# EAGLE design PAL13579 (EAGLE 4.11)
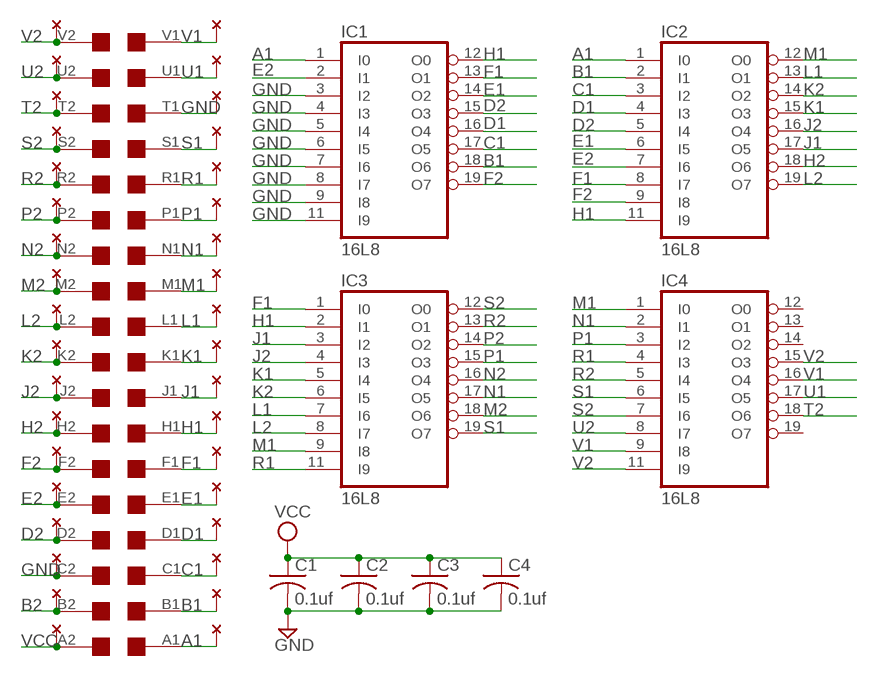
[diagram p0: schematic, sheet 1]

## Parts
C1  0.1uf  C-US050-025X075  [C050-025X075]
C2  0.1uf  C-US050-025X075  [C050-025X075]
C3  0.1uf  C-US050-025X075  [C050-025X075]
C4  0.1uf  C-US050-025X075  [C050-025X075]
IC1  16L8  [DIL20]
IC2  16L8  [DIL20]
IC3  16L8  [DIL20]
IC4  16L8  [DIL20]
U$1  EDGE-2  [EDGE-CON2]
U$4  THRU-HOLE2  [THRU-HOLEB]

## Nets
A1: IC1.1(I0) IC2.1(I0) U$1.A1 U$4.A2
B1: IC1.18(O6) IC2.2(I1) U$1.B1 U$4.B2
B2: U$1.B2 U$4.B1
C1: IC1.17(O5) IC2.3(I2) U$1.C1 U$4.C2
D1: IC1.16(O4) IC2.4(I3) U$1.D1 U$4.D2
D2: IC1.15(O3) IC2.5(I4) U$1.D2 U$4.D1
E1: IC1.14(O2) IC2.6(I5) U$1.E1 U$4.E2
E2: IC1.2(I1) IC2.7(I6) U$1.E2 U$4.E1
F1: IC1.13(O1) IC2.8(I7) IC3.1(I0) U$1.F1 U$4.F2
F2: IC1.19(O7) IC2.9(I8) U$1.F2 U$4.F1
GND [supply]: C1.2 C2.2 C3.2 C4.2 IC1.3(I2) IC1.4(I3) IC1.5(I4) IC1.6(I5) IC1.7(I6) IC1.8(I7) IC1.9(I8) IC1.11(I9) U$1.C2 U$1.T1 U$4.C1 U$4.T2
H1: IC1.12(O0) IC2.11(I9) IC3.2(I1) U$1.H1 U$4.H2
H2: IC2.18(O6) U$1.H2 U$4.H1
J1: IC2.17(O5) IC3.3(I2) U$1.J1 U$4.J2
J2: IC2.16(O4) IC3.4(I3) U$1.J2 U$4.J1
K1: IC2.15(O3) IC3.5(I4) U$1.K1 U$4.K2
K2: IC2.14(O2) IC3.6(I5) U$1.K2 U$4.K1
L1: IC2.13(O1) IC3.7(I6) U$1.L1 U$4.L2
L2: IC2.19(O7) IC3.8(I7) U$1.L2 U$4.L1
M1: IC2.12(O0) IC3.9(I8) IC4.1(I0) U$1.M1 U$4.M2
M2: IC3.18(O6) U$1.M2 U$4.M1
N1: IC3.17(O5) IC4.2(I1) U$1.N1 U$4.N2
N2: IC3.16(O4) U$1.N2 U$4.N1
P1: IC3.15(O3) IC4.3(I2) U$1.P1 U$4.P2
P2: IC3.14(O2) U$1.P2 U$4.P1
R1: IC3.11(I9) IC4.4(I3) U$1.R1 U$4.R2
R2: IC3.13(O1) IC4.5(I4) U$1.R2 U$4.R1
S1: IC3.19(O7) IC4.6(I5) U$1.S1 U$4.S2
S2: IC3.12(O0) IC4.7(I6) U$1.S2 U$4.S1
T2: IC4.18(O6) U$1.T2 U$4.T1
U1: IC4.17(O5) U$1.U1 U$4.U2
U2: IC4.8(I7) U$1.U2 U$4.U1
V1: IC4.9(I8) IC4.16(O4) U$1.V1 U$4.V2
V2: IC4.11(I9) IC4.15(O3) U$1.V2 U$4.V1
VCC [supply]: C1.1 C2.1 C3.1 C4.1 U$1.A2 U$4.A1
Unconnected: IC4.12(O0) IC4.13(O1) IC4.14(O2) IC4.19(O7)

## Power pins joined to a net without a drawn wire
GND: IC1.10(GND) IC2.10(GND) IC3.10(GND) IC4.10(GND)
VCC: IC1.20(VCC) IC2.20(VCC) IC3.20(VCC) IC4.20(VCC)

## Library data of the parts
C1-C4 = rcl:C-US: CAPACITOR, American symbol
IC1-IC4 = pal:16L8: PAL
U$1 = dec-con:EDGE-2: Double-Sided DEC edge connector.
U$4 = dec-con:THRU-HOLE2: Thru-Hole addition to double-sided edge connector.

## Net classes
1 supply: width 0.381 mm

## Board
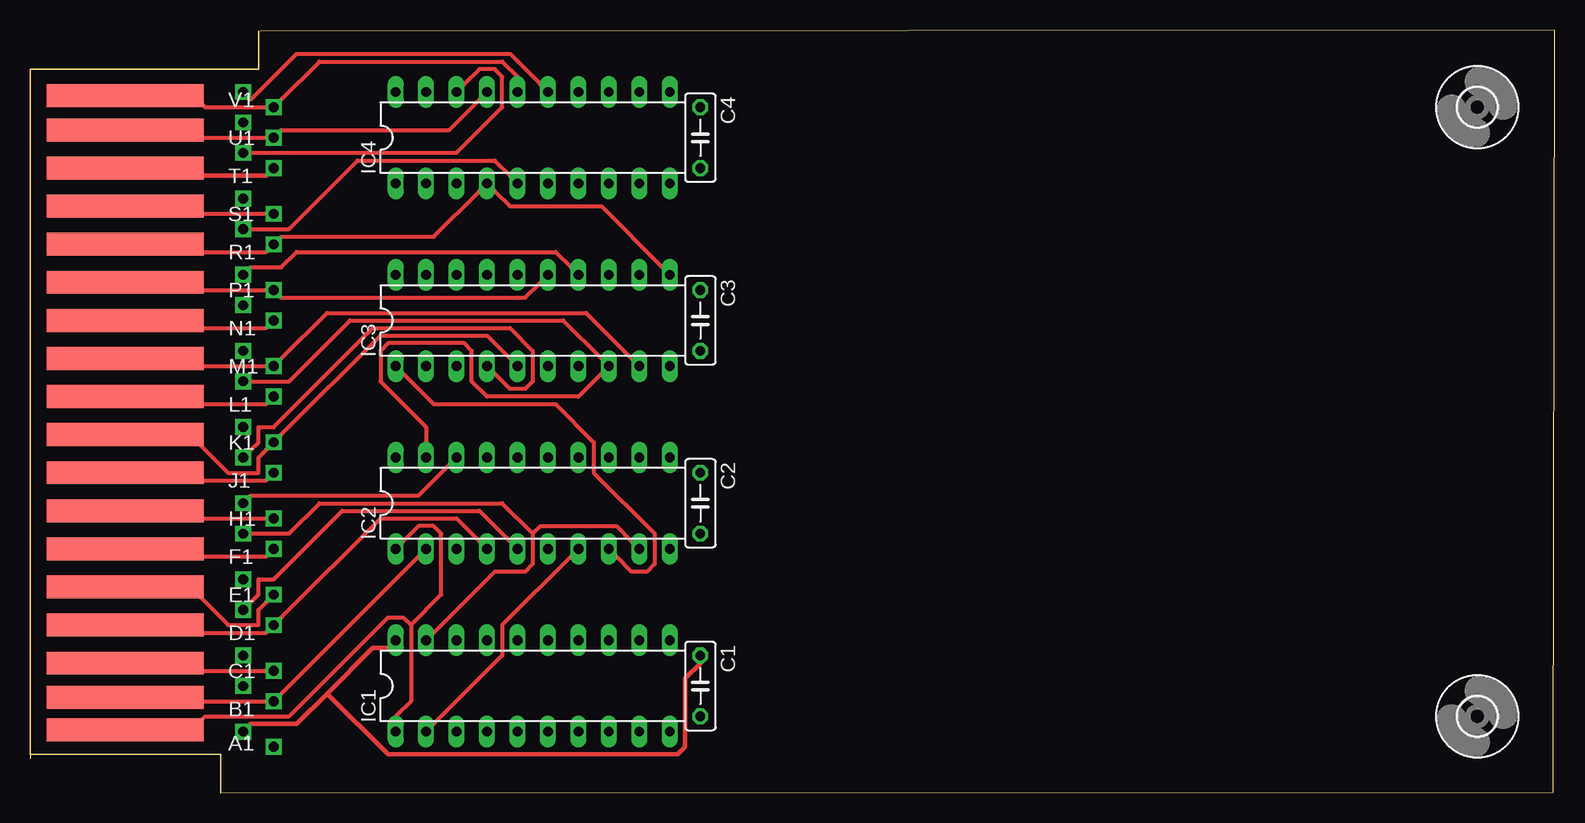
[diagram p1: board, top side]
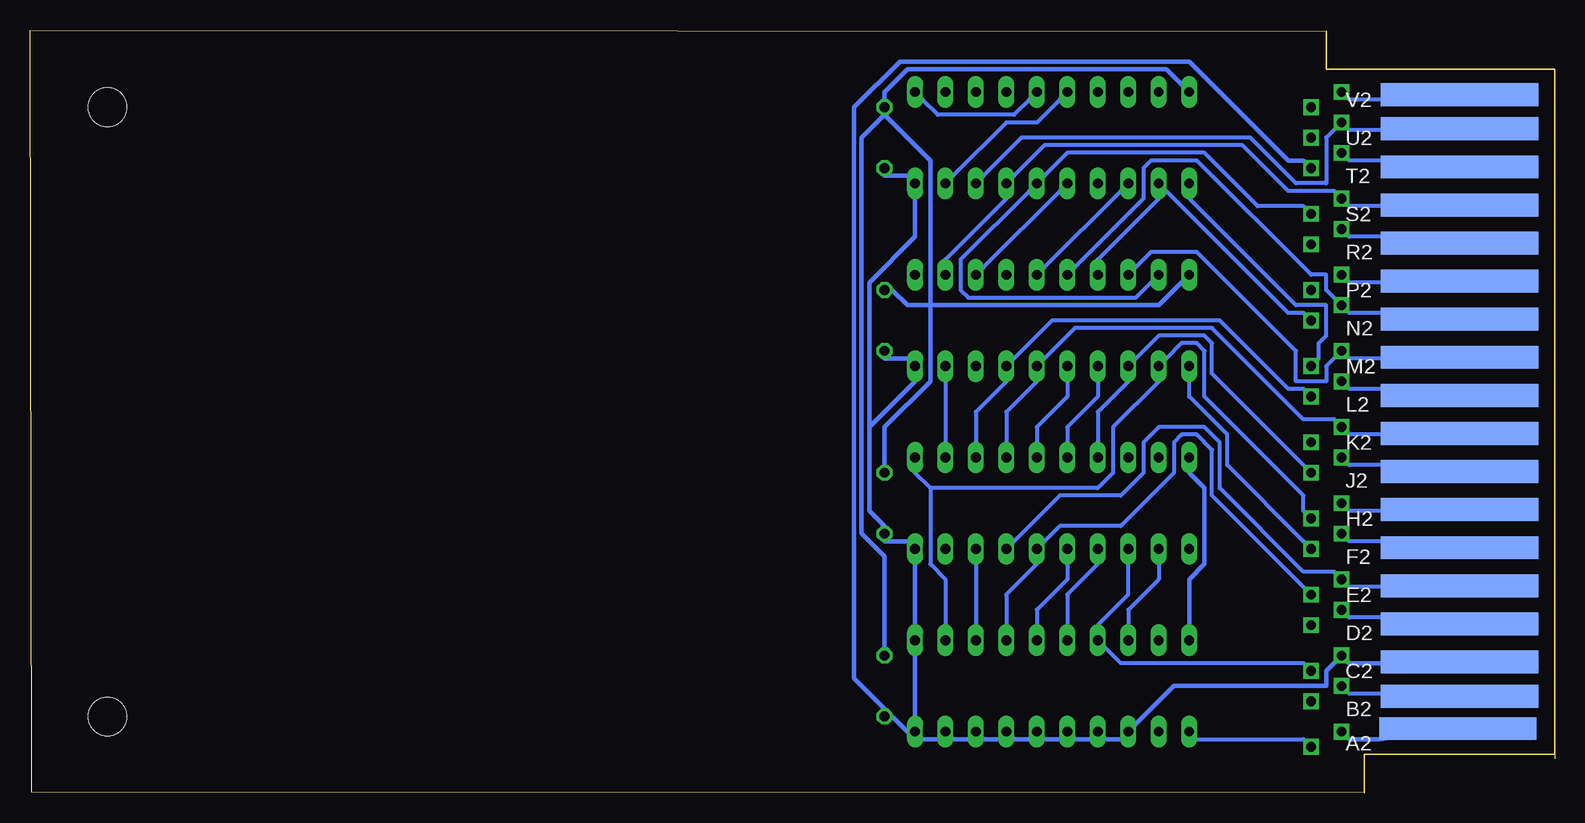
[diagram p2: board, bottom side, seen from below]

Size 127.11 x 63.59 mm. Coordinates in mm from the lower left corner, seen from the top.
Outline: 15.88,0 126.98,0.04 127.11,63.59 19.18,63.5
Outline: 0.01,59.65 0.01,2.83
Copper layers (1*16): Top 0.035mm / dielectric 1.5mm / Bottom 0.035mm
Design rules "10mils": minimum track width 13mil, minimum drill 28mil, track to track 10mil, track to pad 10mil, pad to pad 10mil, via to via 10mil, smd to smd 10mil, copper to edge 40mil, drill to drill 10mil, minimum pad ring 10mil, minimum via ring 8mil, stop-mask expansion 0mil, vias tented up to drill 0mil, thermal gap 10mil

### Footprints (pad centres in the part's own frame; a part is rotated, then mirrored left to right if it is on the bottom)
C050-025X075 = drill 0.813 octagon: 1 -2.54,0; 2 2.54,0
DIL20 = drill 0.813 long: 1 -11.43,-3.81; 2 -8.89,-3.81; 3 -6.35,-3.81; 4 -3.81,-3.81; 5 -1.27,-3.81; 6 1.27,-3.81; 7 3.81,-3.81; 8 6.35,-3.81; 9 8.89,-3.81; 10 11.43,-3.81; 11 11.43,3.81; 12 8.89,3.81; 13 6.35,3.81; 14 3.81,3.81; 15 1.27,3.81; 16 -1.27,3.81; 17 -3.81,3.81; 18 -6.35,3.81; 19 -8.89,3.81; 20 -11.43,3.81
EDGE-CON2 = smd 13.106 x 1.905: A1 7.938,5.239; B1 7.938,7.938; C1 7.938,10.795; D1 7.938,13.97; E1 7.938,17.145; F1 7.938,20.32; H1 7.938,23.495; J1 7.938,26.67; K1 7.938,29.845; L1 7.938,33.02; M1 7.938,36.195; N1 7.938,39.37; P1 7.938,42.545; R1 7.938,45.72; S1 7.938,48.895; T1 7.938,52.07; U1 7.938,55.245; V1 7.938,58.102 | smd 13.106 x 1.905 bottom: A2 8.096,5.34; B2 7.938,8.039; C2 7.938,10.897; D2 7.938,14.072; E2 7.938,17.247; F2 7.938,20.422; H2 7.938,23.597; J2 7.938,26.772; K2 7.938,29.947; L2 7.938,33.122; M2 7.938,36.297; N2 7.938,39.472; P2 7.938,42.647; R2 7.938,45.822; S2 7.938,48.997; T2 7.938,52.172; U2 7.938,55.347; V2 7.938,58.204
3,2 = hole 3.2: 0,0
THRU-HOLEB = drill 0.813 square: A1 17.78,5.08; A2 20.32,3.81; B1 17.78,8.89; B2 20.32,7.62; C1 17.78,11.43; C2 20.32,10.16; D1 17.78,15.24; D2 20.32,13.97; E1 17.78,17.78; E2 20.32,16.51; F1 17.78,21.59; F2 20.32,20.32; H1 17.78,24.13; H2 20.32,22.86; J1 17.78,27.94; J2 20.32,26.67; K1 17.78,30.48; K2 20.32,29.21; L1 17.78,34.29; L2 20.32,33.02; M1 17.78,36.83; M2 20.32,35.56; N1 17.78,40.64; N2 20.32,39.37; P1 17.78,43.18; P2 20.32,41.91; R1 17.78,46.99; R2 20.32,45.72; S1 17.78,49.53; S2 20.32,48.26; T1 17.78,53.34; T2 20.32,52.07; U1 17.78,55.88; U2 20.32,54.61; V1 17.78,58.42; V2 20.32,57.15

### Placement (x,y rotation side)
C1  55.88,8.89 270 top
C2  55.88,24.13 270 top
C3  55.88,39.37 270 top
C4  55.88,54.61 270 top
IC1  41.91,8.89 0 top
IC2  41.91,24.13 0 top
IC3  41.91,39.37 0 top
IC4  41.91,54.61 0 top
U$1  0,0 0 top
U$2  [3,2]  120.65,6.35 0 top
U$3  [3,2]  120.65,57.15 0 top
U$4  0,0 0 top

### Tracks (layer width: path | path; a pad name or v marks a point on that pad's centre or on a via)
A1
  Top 0.33: 31.75,13.97 34.29,16.51 34.29,21.59 33.66,22.23 32.38,22.23 31.11,20.95 IC2.1 | 31.75,13.97 31.75,7.62 30.48,6.35 IC1.1 | 31.75,13.97 31.11,14.61 29.84,14.61 21.59,6.35 14.61,6.35 13.97,5.71 U$1.A1
  Bottom 0.33: U$4.A2 20.95,4.45 29.84,4.45 IC1.1
B1
  Top 0.33: U$1.B1 13.97,7.62 19.68,7.62 U$4.B2 20.95,8.26 32.38,19.68 IC2.2
  Bottom 0.33: IC1.18 35.56,13.97 35.56,15.24 33.02,17.78 33.02,19.05 IC2.2
B2
  Bottom 0.33: U$4.B1 17.14,8.26 13.97,8.26 U$1.B2
C1
  Top 0.33: U$4.C2 19.68,10.16 13.97,10.16 U$1.C1
  Bottom 0.33: U$4.C2 20.95,10.79 36.2,10.79 37.47,12.06 IC1.17 38.1,13.97 35.56,16.51 35.56,19.05 IC2.3
D1
  Top 0.33: U$1.D1 13.97,13.34 19.68,13.34 U$4.D2 20.95,14.61 29.21,22.86 35.56,22.86 37.47,20.95 IC2.4
  Bottom 0.33: IC1.16 40.64,13.97 40.64,16.51 38.1,19.05 IC2.4
D2
  Top 0.33: IC2.5 40.01,20.95 37.47,23.5 26.04,23.5 20.32,17.78 19.05,17.78 19.05,16.51 18.41,15.88 U$4.D1
  Bottom 0.33: IC2.5 40.64,19.05 40.64,17.78 43.18,15.24 43.18,13.97 IC1.15 | U$4.D1 17.14,14.61 13.97,14.61 U$1.D2
E1
  Top 0.33: U$1.E1 13.97,16.51 16.51,13.97 19.05,13.97 19.05,15.24 19.68,15.88 U$4.E2
  Bottom 0.33: U$4.E2 20.95,17.14 28.57,24.77 28.57,28.57 29.84,29.84 31.11,29.84 31.75,29.21 31.75,26.67 36.2,22.23 41.27,22.23 42.55,20.95 IC2.6 43.18,19.05 45.72,16.51 45.72,13.97 IC1.14
E2
  Top 0.33: IC1.2 33.66,5.71 39.37,11.43 39.37,13.97 45.09,19.68 IC2.7
  Bottom 0.33: U$1.E2 13.97,17.14 17.14,17.14 U$4.E1 18.41,18.41 20.95,18.41 27.94,25.4 27.94,29.21 29.21,30.48 33.02,30.48 34.29,29.21 34.29,26.67 36.2,24.77 41.27,24.77 45.09,20.95 IC2.7
F1
  Top 0.33: IC2.8 48.9,19.68 50.16,18.41 51.44,18.41 52.07,19.05 52.07,21.59 46.99,26.67 46.99,29.21 43.81,32.38 33.66,32.38 31.11,34.92 IC3.1 | U$1.F1 13.97,19.68 19.68,19.68 U$4.F2
  Bottom 0.33: IC1.13 48.26,13.97 48.26,19.05 IC2.8 | U$4.F2 20.95,20.95 27.3,27.3 27.3,29.84 30.48,33.02 30.48,34.29 IC3.1
F2
  Top 0.33: 41.91,21.59 41.91,19.05 41.27,18.41 38.73,18.41 33.66,13.34 IC1.19 | 41.91,21.59 42.55,22.23 48.9,22.23 50.16,20.95 IC2.9 | 41.91,21.59 39.37,24.13 24.13,24.13 21.59,21.59 18.41,21.59 U$4.F1
  Bottom 0.33: U$4.F1 17.14,20.95 13.97,20.95 U$1.F2
GND
  Top 0.381: U$4.T2 19.68,51.44 13.97,51.44 U$1.T1
  Bottom 0.381: U$1.C2 13.97,10.79 17.14,10.79 U$4.C1 18.41,10.79 19.05,10.16 19.05,8.89 31.75,8.89 34.92,5.71 IC1.3 36.2,4.45 37.47,4.45 IC1.4 38.73,4.45 40.01,4.45 IC1.5 41.27,4.45 42.55,4.45 IC1.6 43.81,4.45 45.09,4.45 IC1.7 46.35,4.45 47.62,4.45 IC1.8 48.9,4.45 50.16,4.45 IC1.9 51.44,4.45 52.7,4.45 IC1.10 | C4.2 55.88,51.44 53.98,51.44 IC4.10 53.34,49.53 53.34,46.35 57.15,42.55 57.15,30.48 | C3.2 55.88,36.2 53.98,36.2 IC3.10 53.34,34.29 57.15,30.48 | IC1.10 53.98,5.08 55.24,6.35 C1.2 55.88,6.99 58.42,9.53 58.42,57.15 54.61,60.96 30.48,60.96 22.23,52.7 20.95,52.7 U$4.T2 | IC1.10 53.34,6.35 53.34,11.43 IC1.11 53.34,13.97 53.34,19.05 IC2.10 53.98,20.95 55.88,20.95 C2.2 55.88,22.23 57.15,23.5 57.15,30.48
H1
  Top 0.33: U$1.H1 13.97,22.86 19.68,22.86 U$4.H2
  Bottom 0.33: 52.07,25.4 52.07,19.05 50.8,17.78 50.8,13.97 IC1.12 | 52.07,25.4 53.34,26.67 IC2.11 | U$4.H2 20.95,23.5 20.95,24.77 29.21,33.02 29.21,36.83 29.84,37.47 31.11,37.47 32.38,36.2 IC3.2 33.02,34.29 36.83,30.48 36.83,26.67 38.1,25.4 52.07,25.4
H2
  Top 0.33: IC2.18 34.92,27.3 32.38,24.77 18.41,24.77 U$4.H1
  Bottom 0.33: U$4.H1 17.14,23.5 13.97,23.5 U$1.H2
J1
  Top 0.33: U$4.J2 19.68,26.04 13.97,26.04 U$1.J1
  Bottom 0.33: U$4.J2 20.95,27.3 28.57,34.92 28.57,37.47 29.21,38.1 33.02,38.1 34.92,36.2 IC3.3 35.56,34.29 38.1,31.75 38.1,29.21 IC2.17
J2
  Top 0.33: IC3.4 38.73,34.92 40.01,33.66 41.27,33.66 41.91,34.29 41.91,36.83 40.01,38.73 28.57,38.73 20.32,30.48 19.05,30.48 19.05,29.21 18.41,28.57 U$4.J1
  Bottom 0.33: IC3.4 38.1,34.29 38.1,33.02 40.64,30.48 40.64,29.21 IC2.16 | U$4.J1 17.14,27.3 13.97,27.3 U$1.J2
K1
  Top 0.33: U$1.K1 13.97,29.21 16.51,26.67 19.05,26.67 19.05,27.94 19.68,28.57 U$4.K2 20.95,29.84 29.21,38.1 38.1,38.1 40.01,36.2 IC3.5
  Bottom 0.33: IC3.5 40.64,34.29 40.64,33.02 43.18,30.48 43.18,29.21 IC2.15
K2
  Bottom 0.33: IC2.14 45.72,29.21 45.72,31.75 43.18,34.29 IC3.6 42.55,36.2 40.01,38.73 28.57,38.73 20.95,31.11 18.41,31.11 U$4.K1 17.14,29.84 13.97,29.84 U$1.K2
L1
  Top 0.33: U$1.L1 13.97,32.38 19.68,32.38 U$4.L2
  Bottom 0.33: U$4.L2 20.95,33.66 22.23,33.66 27.94,39.37 41.91,39.37 45.09,36.2 IC3.7 45.72,34.29 48.26,31.75 48.26,29.21 IC2.13
L2
  Top 0.33: IC2.19 33.02,29.21 33.02,30.48 29.21,34.29 29.21,36.83 29.84,37.47 36.2,37.47 36.83,36.83 36.83,34.29 38.1,33.02 45.72,33.02 47.62,34.92 IC3.8 47.62,36.2 44.45,39.37 26.67,39.37 21.59,34.29 18.41,34.29 U$4.L1
  Bottom 0.33: U$4.L1 17.14,33.66 13.97,33.66 U$1.L2
M1
  Top 0.33: IC3.9 50.16,36.2 46.35,40.01 24.77,40.01 20.95,36.2 U$4.M2 19.68,35.56 13.97,35.56 U$1.M1
  Bottom 0.33: IC2.12 50.8,29.21 50.8,34.29 IC3.9 | U$4.M2 19.68,36.2 19.68,37.47 19.05,38.1 19.05,40.64 21.59,40.64 30.48,49.53 IC4.1
M2
  Bottom 0.33: U$1.M2 13.97,36.2 17.14,36.2 U$4.M1 18.41,36.2 19.05,35.56 19.05,34.29 21.59,34.29 21.59,36.83 29.84,45.09 33.66,45.09 34.92,43.81 IC3.18
N1
  Top 0.33: U$4.N2 19.68,38.73 13.97,38.73 U$1.N1
  Bottom 0.33: U$4.N2 20.95,40.01 22.23,40.01 32.38,50.16 IC4.2 33.02,49.53 38.1,44.45 IC3.17
N2
  Bottom 0.33: U$1.N2 13.97,40.01 17.14,40.01 U$4.N1 18.41,41.27 19.05,41.91 19.05,43.18 20.32,43.18 29.84,52.7 33.66,52.7 34.29,52.07 34.29,49.53 40.01,43.81 IC3.16
P1
  Top 0.33: U$1.P1 13.97,41.91 19.68,41.91 U$4.P2 20.95,41.27 41.27,41.27 42.55,42.55 IC3.15
  Bottom 0.33: IC3.15 42.55,43.81 36.2,50.16 IC4.3
P2
  Top 0.33: IC3.14 45.09,43.81 43.81,45.09 22.23,45.09 20.95,43.81 18.41,43.81 U$4.P1
  Bottom 0.33: U$4.P1 17.14,42.55 13.97,42.55 U$1.P2
R1
  Top 0.33: IC3.11 52.7,43.81 47.62,48.9 40.01,48.9 38.73,50.16 IC4.4 37.47,50.16 33.66,46.35 20.95,46.35 U$4.R2 19.68,45.09 13.97,45.09 U$1.R1
R2
  Top 0.33: IC4.5 40.01,51.44 38.73,52.7 27.3,52.7 21.59,46.99 18.41,46.99 U$4.R1
  Bottom 0.33: IC3.13 47.62,43.81 41.27,50.16 IC4.5 | U$4.R1 17.14,46.35 13.97,46.35 U$1.R2
S1
  Top 0.33: U$1.S1 13.97,48.26 19.68,48.26 U$4.S2
  Bottom 0.33: U$4.S2 20.95,48.9 24.77,48.9 29.21,53.34 40.64,53.34 42.55,51.44 IC4.6 43.81,50.16 49.53,44.45 49.53,41.91 48.9,41.27 34.92,41.27 33.66,42.55 IC3.19
S2
  Bottom 0.33: IC3.12 50.8,44.45 45.72,49.53 IC4.7 45.09,51.44 42.55,53.98 26.04,53.98 22.23,50.16 18.41,50.16 U$4.S1 17.14,48.9 13.97,48.9 U$1.S2
T2
  Top 0.33: IC4.18 36.2,59.05 37.47,60.33 38.73,60.33 39.37,59.69 39.37,57.15 35.56,53.34 18.41,53.34 U$4.T1
  Bottom 0.33: U$4.T1 17.14,52.7 13.97,52.7 U$1.T2
U1
  Top 0.33: U$1.U1 13.97,54.61 19.68,54.61 U$4.U2 20.95,55.24 34.92,55.24 37.47,57.78 IC4.17
U2
  Bottom 0.33: U$1.U2 13.97,55.24 17.14,55.24 U$4.U1 18.41,55.24 19.05,54.61 19.05,50.8 21.59,50.8 25.4,54.61 44.45,54.61 47.62,51.44 IC4.8
V1
  Top 0.33: U$1.V1 13.97,57.78 14.61,57.15 19.68,57.15 U$4.V2 20.95,57.78 24.13,60.96 39.37,60.96 40.64,59.69 IC4.16
  Bottom 0.33: IC4.9 50.16,51.44 45.72,55.88 43.18,55.88 41.27,57.78 IC4.16
V2
  Top 0.33: IC4.15 42.55,59.05 40.01,61.59 22.23,61.59 18.41,57.78 U$4.V1
  Bottom 0.33: IC4.15 43.81,57.78 45.09,56.52 51.44,56.52 52.7,57.78 IC4.11 | U$4.V1 17.14,57.78 13.97,57.78 U$1.V2
VCC
  Top 0.381: 24.77,8.26 22.23,5.71 18.41,5.71 U$4.A1 | 24.77,8.26 28.57,12.06 29.84,12.06 IC1.20 | 24.77,8.26 29.84,3.17 53.98,3.17 54.61,3.81 54.61,9.53 55.88,10.79 C1.1
  Bottom 0.381: IC1.20 30.48,13.97 30.48,17.78 29.21,19.05 29.21,25.4 30.48,26.67 IC2.20 | U$4.A1 17.14,4.45 14.61,4.45 U$1.A2 | 52.07,40.64 53.98,40.64 55.24,41.91 C3.1 | 52.07,40.64 33.02,40.64 31.11,42.55 IC3.20 | 52.07,40.64 52.07,34.29 55.88,30.48 55.88,27.3 C2.1 | 55.88,56.52 57.78,54.61 57.78,21.59 55.88,19.68 55.88,12.06 C1.1 | 55.88,56.52 C4.1 | IC4.20 31.11,59.05 32.38,60.33 53.98,60.33 55.88,58.42 55.88,57.78 C4.1 | 52.07,40.64 52.07,52.7 55.88,56.52 | 55.88,56.52 C4.1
